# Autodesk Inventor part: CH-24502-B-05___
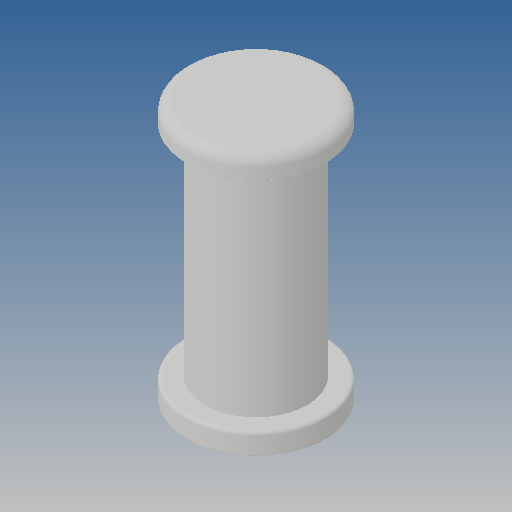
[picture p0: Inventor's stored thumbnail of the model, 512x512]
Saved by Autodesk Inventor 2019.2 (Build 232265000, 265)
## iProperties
Created: 2010-06
Part Number: CH-24502-B-05___
Material: Ogólny
Document SubType Name: Modeling
Designer: CADENGINEERING4
Density: 1 g/cm^3
Appearance: Domyślna
Author: CADENGINEERING4
Revision Number: ANY
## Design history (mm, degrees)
feature "NONE"
node "Bryła1"
